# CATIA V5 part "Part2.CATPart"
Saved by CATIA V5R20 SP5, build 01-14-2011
Part number: Part2
Bounding box of the stored display mesh (mm): x -24.106 to 24.106, y -24.096 to 24.1, z 0 to 80
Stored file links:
  C:\Users\wcz0113\Desktop\Part2.CATPart
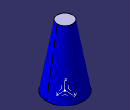
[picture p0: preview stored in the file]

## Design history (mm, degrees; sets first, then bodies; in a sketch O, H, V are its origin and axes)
AxisSystem1: origin (0, 0, 0), X (1, 0, 0), Y (0, 1, 0), Z (0, 0, 1)
Body1 (main body)
  Sketch1 on xy-plane, origin (0, 0, 0), H (1, 0, 0), V (0, 1, 0)
    circle A1 centre (0, 0) radius 10
    reference projected point E1 (0, 0) from vertex [YZ plane of AxisSystem1 | ZX plane of AxisSystem1 | XY plane of AxisSystem1]
    radius A1 = 10
    concentricity: E1 A1
  Pad1: profile Sketch1, direction (0, 0, 1), length 80
  Draft1: Angle 10, Neutral end face of Pad1, PullDir end face of Pad1, SupportToDraft face of Pad1 from Sketch1.A1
